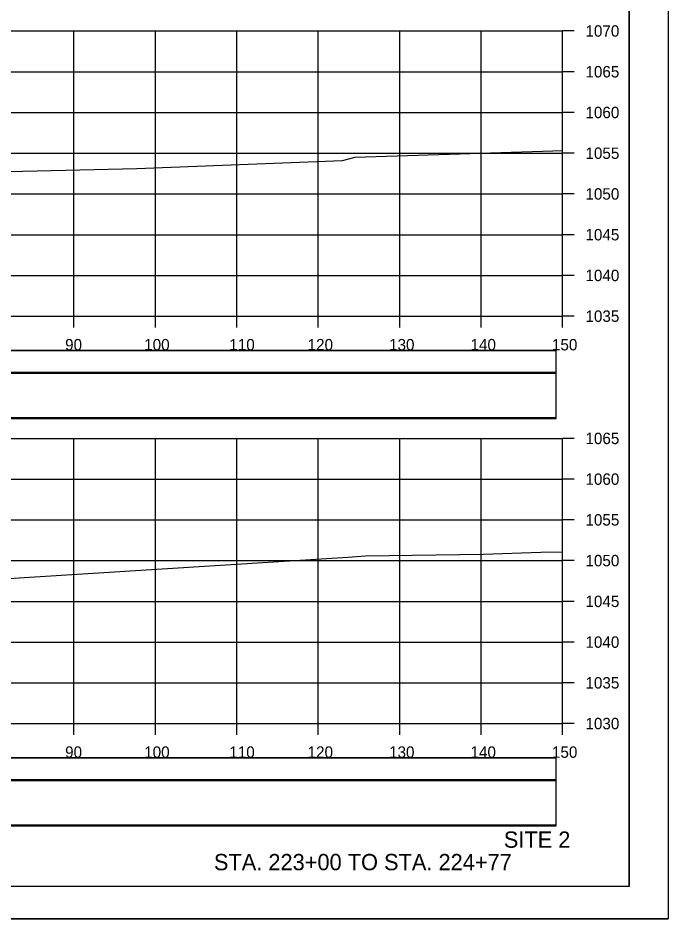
# Model space of a CAD drawing. Extents: x 1370565 to 1374448, y 301010 to 304637.
# Drawn here: x 1373451.9 to 1373531.7, y 303218.4 to 303328.9 of the extents above; entities that cross this region are included whole.
import ezdxf

# ---------------------------------------------------------------- set-up
doc = ezdxf.new("R2010")
doc.units = 0
for name, color, linetype in [('Default', 7, 'Continuous'), ('R_Axis', 7, 'Continuous'), ('R_Axis Annot', 7, 'Continuous'), ('R_Border', 7, 'Continuous'), ('R_Draft', 7, 'Continuous'), ('R_Drive', 7, 'Continuous'), ('R_Exist Surface', 7, 'Continuous'), ('R_Grid', 7, 'Continuous'), ('R_No Plot', 7, 'Continuous')]:
    doc.layers.add(name, color=color, linetype=linetype)

msp = doc.modelspace()

# ---------------------------------------------------------------- linework, layer by layer
at = {"layer": 'Default'}
for points in [[(1373219.61, 303285.38), (1373518.02, 303285.38), (1373518.02, 303288.08), (1373219.61, 303288.08)], [(1373219.61, 303279.8), (1373518.02, 303279.8), (1373518.02, 303285.32), (1373219.61, 303285.32)], [(1373219.61, 303235.38), (1373518.02, 303235.38), (1373518.02, 303238.08), (1373219.61, 303238.08)], [(1373219.61, 303229.8), (1373518.02, 303229.8), (1373518.02, 303235.32), (1373219.61, 303235.32)]]:
    msp.add_lwpolyline(points, close=True, dxfattribs=at)
at = {"layer": 'R_Axis'}
for p, q in [((1373518.81, 303292.34), (1373518.81, 303327.34)), ((1373520.21, 303327.34), (1373518.81, 303327.34)), ((1373520.21, 303322.34), (1373518.81, 303322.34)), ((1373520.21, 303317.34), (1373518.81, 303317.34)), ((1373520.21, 303312.34), (1373518.81, 303312.34)), ((1373520.21, 303307.34), (1373518.81, 303307.34)), ((1373520.21, 303302.34), (1373518.81, 303302.34)), ((1373520.21, 303297.34), (1373518.81, 303297.34)), ((1373218.81, 303292.34), (1373518.81, 303292.34)), ((1373458.81, 303290.94), (1373458.81, 303292.34)), ((1373468.81, 303290.94), (1373468.81, 303292.34)), ((1373478.81, 303290.94), (1373478.81, 303292.34)), ((1373488.81, 303290.94), (1373488.81, 303292.34)), ((1373498.81, 303290.94), (1373498.81, 303292.34)), ((1373508.81, 303290.94), (1373508.81, 303292.34)), ((1373518.81, 303290.94), (1373518.81, 303292.34)), ((1373520.21, 303292.34), (1373518.81, 303292.34)), ((1373518.81, 303242.34), (1373518.81, 303277.34)), ((1373520.21, 303277.34), (1373518.81, 303277.34)), ((1373520.21, 303272.34), (1373518.81, 303272.34)), ((1373520.21, 303267.34), (1373518.81, 303267.34)), ((1373520.21, 303262.34), (1373518.81, 303262.34)), ((1373520.21, 303257.34), (1373518.81, 303257.34)), ((1373520.21, 303252.34), (1373518.81, 303252.34)), ((1373520.21, 303247.34), (1373518.81, 303247.34)), ((1373218.81, 303242.34), (1373518.81, 303242.34)), ((1373458.81, 303240.94), (1373458.81, 303242.34)), ((1373468.81, 303240.94), (1373468.81, 303242.34)), ((1373478.81, 303240.94), (1373478.81, 303242.34)), ((1373488.81, 303240.94), (1373488.81, 303242.34)), ((1373498.81, 303240.94), (1373498.81, 303242.34)), ((1373508.81, 303240.94), (1373508.81, 303242.34)), ((1373518.81, 303240.94), (1373518.81, 303242.34)), ((1373520.21, 303242.34), (1373518.81, 303242.34))]:
    msp.add_line(p, q, dxfattribs=at)
at = {"layer": 'R_Border'}
for q in [(1373526.99, 303427.8), (1373210.81, 303222.34)]:
    msp.add_line((1373526.99, 303222.34), q, dxfattribs=at)
at = {"layer": 'R_Drive'}
for points in [[(1373219.61, 303285.43), (1373518.02, 303285.43), (1373518.02, 303288.14), (1373219.61, 303288.14)], [(1373219.61, 303279.91), (1373518.02, 303279.91), (1373518.02, 303285.43), (1373219.61, 303285.43)], [(1373219.61, 303235.43), (1373518.02, 303235.43), (1373518.02, 303238.14), (1373219.61, 303238.14)], [(1373219.61, 303229.91), (1373518.02, 303229.91), (1373518.02, 303235.43), (1373219.61, 303235.43)]]:
    msp.add_lwpolyline(points, close=True, dxfattribs=at)
at = {"layer": 'R_Exist Surface'}
for points in [[(1373435, 303309.72), (1373466.52, 303310.48), (1373491.78, 303311.43), (1373493.16, 303311.82), (1373493.31, 303311.86), (1373498.5, 303312.03), (1373517.62, 303312.62), (1373518.81, 303312.66)], [(1373301.02, 303258.44), (1373320.91, 303258.53), (1373357.1, 303258.73), (1373368.6, 303257.11), (1373372.14, 303256.59), (1373375.76, 303257.12), (1373387.84, 303258.93), (1373394.39, 303259.08), (1373398.15, 303259.16), (1373402.11, 303259.07), (1373407.92, 303258.95), (1373416.86, 303258.13), (1373425.13, 303257.3), (1373437.42, 303259.09), (1373439.83, 303259.42), (1373452.69, 303260.26), (1373492.44, 303262.76), (1373494.61, 303262.94), (1373509.05, 303263.14), (1373516.13, 303263.36), (1373518.78, 303263.41), (1373518.81, 303263.41)]]:
    msp.add_lwpolyline(points, dxfattribs=at)
at = {"layer": 'R_Grid'}
for p, q in [((1373218.81, 303327.34), (1373518.81, 303327.34)), ((1373458.81, 303292.34), (1373458.81, 303327.34)), ((1373468.81, 303292.34), (1373468.81, 303327.34)), ((1373478.81, 303292.34), (1373478.81, 303327.34)), ((1373488.81, 303292.34), (1373488.81, 303327.34)), ((1373498.81, 303292.34), (1373498.81, 303327.34)), ((1373508.81, 303292.34), (1373508.81, 303327.34)), ((1373518.81, 303292.34), (1373518.81, 303327.34)), ((1373218.81, 303322.34), (1373518.81, 303322.34)), ((1373218.81, 303317.34), (1373518.81, 303317.34)), ((1373218.81, 303312.34), (1373518.81, 303312.34)), ((1373218.81, 303307.34), (1373518.81, 303307.34)), ((1373218.81, 303302.34), (1373518.81, 303302.34)), ((1373218.81, 303297.34), (1373518.81, 303297.34)), ((1373218.81, 303292.34), (1373518.81, 303292.34)), ((1373218.81, 303277.34), (1373518.81, 303277.34)), ((1373458.81, 303242.34), (1373458.81, 303277.34)), ((1373468.81, 303242.34), (1373468.81, 303277.34)), ((1373478.81, 303242.34), (1373478.81, 303277.34)), ((1373488.81, 303242.34), (1373488.81, 303277.34)), ((1373498.81, 303242.34), (1373498.81, 303277.34)), ((1373508.81, 303242.34), (1373508.81, 303277.34)), ((1373518.81, 303242.34), (1373518.81, 303277.34)), ((1373218.81, 303272.34), (1373518.81, 303272.34)), ((1373218.81, 303267.34), (1373518.81, 303267.34)), ((1373218.81, 303262.34), (1373518.81, 303262.34)), ((1373218.81, 303257.34), (1373518.81, 303257.34)), ((1373218.81, 303252.34), (1373518.81, 303252.34)), ((1373218.81, 303247.34), (1373518.81, 303247.34)), ((1373218.81, 303242.34), (1373518.81, 303242.34))]:
    msp.add_line(p, q, dxfattribs=at)
at = {"layer": 'R_No Plot'}
msp.add_line((1373198.41, 303218.36), (1373531.75, 303218.36), dxfattribs=at)
for points in [[(1373198.41, 303431.69), (1373531.75, 303431.69), (1373531.75, 303218.36), (1373198.41, 303218.36)], [(1373444.73, 303427.8), (1373464.35, 303427.8), (1373464.35, 303417.92), (1373480.47, 303417.92), (1373503.67, 303417.92), (1373503.67, 303393.59), (1373526.99, 303393.59), (1373526.99, 303222.34), (1373210.81, 303222.34), (1373210.81, 303427.8)]]:
    msp.add_lwpolyline(points, close=True, dxfattribs=at)

# ---------------------------------------------------------------- texts
at = {"layer": 'R_Axis Annot'}
for s, p in [('1070', (1373521.61, 303326.64)), ('1065', (1373521.61, 303321.64)), ('1060', (1373521.61, 303316.64)), ('1055', (1373521.61, 303311.64)), ('1050', (1373521.61, 303306.64)), ('1045', (1373521.61, 303301.64)), ('1040', (1373521.61, 303296.64)), ('1035', (1373521.61, 303291.64)), ('90', (1373457.73, 303288.14)), ('100', (1373467.44, 303288.14)), ('110', (1373477.89, 303288.14)), ('120', (1373487.5, 303288.14)), ('130', (1373497.5, 303288.14)), ('140', (1373507.5, 303288.14)), ('150', (1373517.5, 303288.14)), ('1065', (1373521.61, 303276.64)), ('1060', (1373521.61, 303271.64)), ('1055', (1373521.61, 303266.64)), ('1050', (1373521.61, 303261.64)), ('1045', (1373521.61, 303256.64)), ('1040', (1373521.61, 303251.64)), ('1035', (1373521.61, 303246.64)), ('1030', (1373521.61, 303241.64)), ('90', (1373457.73, 303238.14)), ('100', (1373467.44, 303238.14)), ('110', (1373477.89, 303238.14)), ('120', (1373487.5, 303238.14)), ('130', (1373497.5, 303238.14)), ('140', (1373507.5, 303238.14)), ('150', (1373517.5, 303238.14))]:
    msp.add_text(s, height=1.4, dxfattribs=at).set_placement(p)
at = {"layer": 'R_Draft'}
for s, p in [('SITE 2', (1373511.59, 303227.1)), ('STA. 223+00 TO STA. 224+77', (1373476, 303224.34))]:
    msp.add_text(s, height=2, dxfattribs=at).set_placement(p)

doc.saveas('drawing.dxf')
